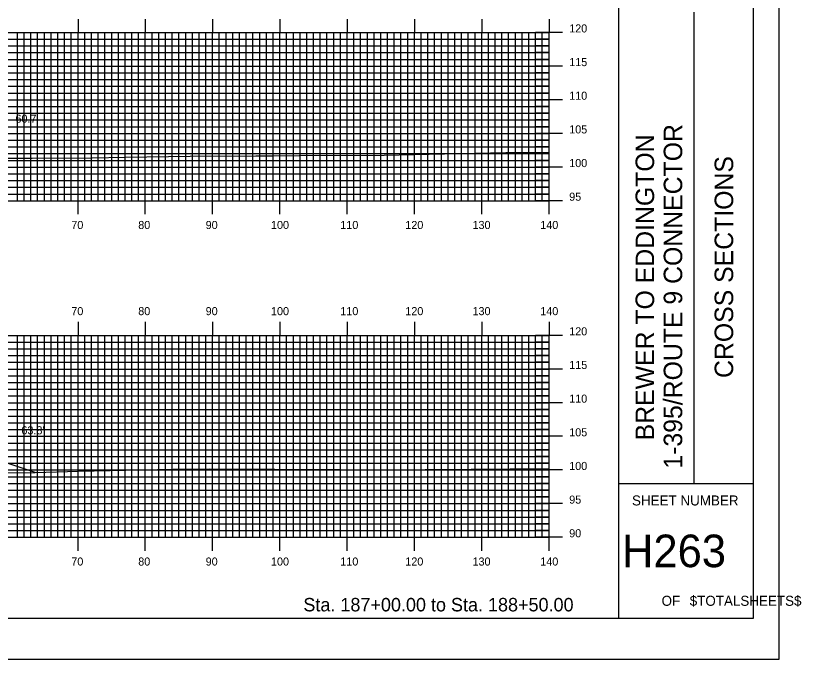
# Model space of a CAD drawing. Extents: x 1787763 to 1788106, y 442591 to 442811.
# Drawn here: x 1787989.4 to 1788106.1, y 442590.5 to 442686.2 of the extents above; entities that cross this region are included whole.
import ezdxf

# ---------------------------------------------------------------- set-up
doc = ezdxf.new("R2010")
doc.units = 0
for name, color, linetype in [('BORDER', 7, 'Continuous'), ('D_Roadway_Centerline', 7, 'Continuous'), ('D_Roadway_SlopeLines', 7, 'Continuous'), ('D_Text_Standard', 7, 'Continuous'), ('H_V ANNOTATION', 7, 'Continuous'), ('MAJOR', 7, 'Continuous'), ('MINOR', 7, 'Continuous'), ('PLOT BOUNDARY', 7, 'Continuous'), ('S_Roadway_Centerline', 7, 'Continuous')]:
    doc.layers.add(name, color=color, linetype=linetype)

msp = doc.modelspace()

# ---------------------------------------------------------------- linework, layer by layer
at = {"layer": 'BORDER'}
for p, q in [((1788079.02, 442596.67), (1788079.02, 442806.67)), ((1788090.2, 442616.67), (1788090.2, 442686.67)), ((1788079.02, 442616.67), (1788099.02, 442616.67))]:
    msp.add_line(p, q, dxfattribs=at)
msp.add_lwpolyline([(1787779.02, 442596.67), (1788099.02, 442596.67), (1788099.02, 442806.67), (1787779.02, 442806.67)], close=True, dxfattribs=at)
at = {"layer": 'D_Roadway_Centerline'}
msp.add_lwpolyline([(1787864.55, 442617.68), (1787896.62, 442628.37), (1787900.25, 442629.27), (1787908.62, 442631.37), (1787916.62, 442631.69), (1787928.62, 442631.95), (1787940.62, 442632.21), (1787948.62, 442631.89), (1787956.98, 442629.8), (1787960.62, 442628.89), (1787992.37, 442618.31)], dxfattribs=at)
at = {"layer": 'D_Roadway_SlopeLines'}
msp.add_lwpolyline([(1787948.62, 442631.89), (1787960.62, 442628.89), (1787992.37, 442618.31)], dxfattribs=at)
at = {"layer": 'MAJOR'}
for p, q in [((1787998.62, 442685.67), (1787998.62, 442683.67)), ((1788008.62, 442685.67), (1788008.62, 442683.67)), ((1788018.62, 442685.67), (1788018.62, 442683.67)), ((1788028.62, 442685.67), (1788028.62, 442683.67)), ((1788038.62, 442685.67), (1788038.62, 442683.67)), ((1788048.62, 442685.67), (1788048.62, 442683.67)), ((1788058.62, 442685.67), (1788058.62, 442683.67)), ((1788068.62, 442685.67), (1788068.62, 442683.67)), ((1787788.62, 442683.67), (1788068.62, 442683.67)), ((1787788.62, 442683.67), (1788068.62, 442683.67)), ((1787998.62, 442658.67), (1787998.62, 442683.67)), ((1788008.62, 442658.67), (1788008.62, 442683.67)), ((1788018.62, 442658.67), (1788018.62, 442683.67)), ((1788028.62, 442658.67), (1788028.62, 442683.67)), ((1788038.62, 442658.67), (1788038.62, 442683.67)), ((1788048.62, 442658.67), (1788048.62, 442683.67)), ((1788058.62, 442658.67), (1788058.62, 442683.67)), ((1788070.62, 442683.67), (1788066.61, 442683.67)), ((1788068.62, 442658.67), (1788068.62, 442683.67)), ((1788068.62, 442658.67), (1788068.62, 442683.67)), ((1787788.62, 442678.67), (1788068.62, 442678.67)), ((1788070.62, 442678.67), (1788066.61, 442678.67)), ((1787788.62, 442673.67), (1788068.62, 442673.67)), ((1788070.62, 442673.67), (1788066.61, 442673.67)), ((1787788.62, 442668.67), (1788068.62, 442668.67)), ((1788070.62, 442668.67), (1788066.61, 442668.67)), ((1787788.62, 442663.67), (1788068.62, 442663.67)), ((1788070.62, 442663.67), (1788066.61, 442663.67)), ((1787788.62, 442658.67), (1788068.62, 442658.67)), ((1787788.62, 442658.67), (1788068.62, 442658.67)), ((1787998.62, 442656.66), (1787998.62, 442658.67)), ((1788008.62, 442656.66), (1788008.62, 442658.67)), ((1788018.62, 442656.66), (1788018.62, 442658.67)), ((1788028.62, 442656.66), (1788028.62, 442658.67)), ((1788038.62, 442656.66), (1788038.62, 442658.67)), ((1788048.62, 442656.66), (1788048.62, 442658.67)), ((1788058.62, 442656.66), (1788058.62, 442658.67)), ((1788070.62, 442658.67), (1788066.61, 442658.67)), ((1788068.62, 442656.66), (1788068.62, 442658.67)), ((1787998.62, 442640.67), (1787998.62, 442638.67)), ((1788008.62, 442640.67), (1788008.62, 442638.67)), ((1788018.62, 442640.67), (1788018.62, 442638.67)), ((1788028.62, 442640.67), (1788028.62, 442638.67)), ((1788038.62, 442640.67), (1788038.62, 442638.67)), ((1788048.62, 442640.67), (1788048.62, 442638.67)), ((1788058.62, 442640.67), (1788058.62, 442638.67)), ((1788068.62, 442640.67), (1788068.62, 442638.67)), ((1787788.62, 442638.67), (1788068.62, 442638.67)), ((1787788.62, 442638.67), (1788068.62, 442638.67)), ((1787998.62, 442608.67), (1787998.62, 442638.67)), ((1788008.62, 442608.67), (1788008.62, 442638.67)), ((1788018.62, 442608.67), (1788018.62, 442638.67)), ((1788028.62, 442608.67), (1788028.62, 442638.67)), ((1788038.62, 442608.67), (1788038.62, 442638.67)), ((1788048.62, 442608.67), (1788048.62, 442638.67)), ((1788058.62, 442608.67), (1788058.62, 442638.67)), ((1788070.62, 442638.67), (1788066.61, 442638.67)), ((1788068.62, 442608.67), (1788068.62, 442638.67)), ((1788068.62, 442608.67), (1788068.62, 442638.67)), ((1787788.62, 442633.67), (1788068.62, 442633.67)), ((1788070.62, 442633.67), (1788066.61, 442633.67)), ((1787788.62, 442628.67), (1788068.62, 442628.67)), ((1788070.62, 442628.67), (1788066.61, 442628.67)), ((1787788.62, 442623.67), (1788068.62, 442623.67)), ((1788070.62, 442623.67), (1788066.61, 442623.67)), ((1787788.62, 442618.67), (1788068.62, 442618.67)), ((1788070.62, 442618.67), (1788066.61, 442618.67)), ((1787788.62, 442613.67), (1788068.62, 442613.67)), ((1788070.62, 442613.67), (1788066.61, 442613.67)), ((1787788.62, 442608.67), (1788068.62, 442608.67)), ((1787788.62, 442608.67), (1788068.62, 442608.67)), ((1787998.62, 442606.66), (1787998.62, 442608.67)), ((1788008.62, 442606.66), (1788008.62, 442608.67)), ((1788018.62, 442606.66), (1788018.62, 442608.67)), ((1788028.62, 442606.66), (1788028.62, 442608.67)), ((1788038.62, 442606.66), (1788038.62, 442608.67)), ((1788048.62, 442606.66), (1788048.62, 442608.67)), ((1788058.62, 442606.66), (1788058.62, 442608.67)), ((1788070.62, 442608.67), (1788066.61, 442608.67)), ((1788068.62, 442606.66), (1788068.62, 442608.67))]:
    msp.add_line(p, q, dxfattribs=at)
at = {"layer": 'MINOR'}
for p, q in [((1787788.62, 442682.67), (1788068.62, 442682.67)), ((1787989.62, 442658.67), (1787989.62, 442683.67)), ((1787990.62, 442658.67), (1787990.62, 442683.67)), ((1787991.62, 442658.67), (1787991.62, 442683.67)), ((1787992.62, 442658.67), (1787992.62, 442683.67)), ((1787993.62, 442658.67), (1787993.62, 442683.67)), ((1787994.62, 442658.67), (1787994.62, 442683.67)), ((1787995.62, 442658.67), (1787995.62, 442683.67)), ((1787996.62, 442658.67), (1787996.62, 442683.67)), ((1787997.62, 442658.67), (1787997.62, 442683.67)), ((1787999.62, 442658.67), (1787999.62, 442683.67)), ((1788000.62, 442658.67), (1788000.62, 442683.67)), ((1788001.62, 442658.67), (1788001.62, 442683.67)), ((1788002.62, 442658.67), (1788002.62, 442683.67)), ((1788003.62, 442658.67), (1788003.62, 442683.67)), ((1788004.62, 442658.67), (1788004.62, 442683.67)), ((1788005.62, 442658.67), (1788005.62, 442683.67)), ((1788006.62, 442658.67), (1788006.62, 442683.67)), ((1788007.62, 442658.67), (1788007.62, 442683.67)), ((1788009.62, 442658.67), (1788009.62, 442683.67)), ((1788010.62, 442658.67), (1788010.62, 442683.67)), ((1788011.62, 442658.67), (1788011.62, 442683.67)), ((1788012.62, 442658.67), (1788012.62, 442683.67)), ((1788013.62, 442658.67), (1788013.62, 442683.67)), ((1788014.62, 442658.67), (1788014.62, 442683.67)), ((1788015.62, 442658.67), (1788015.62, 442683.67)), ((1788016.62, 442658.67), (1788016.62, 442683.67)), ((1788017.62, 442658.67), (1788017.62, 442683.67)), ((1788019.62, 442658.67), (1788019.62, 442683.67)), ((1788020.62, 442658.67), (1788020.62, 442683.67)), ((1788021.62, 442658.67), (1788021.62, 442683.67)), ((1788022.62, 442658.67), (1788022.62, 442683.67)), ((1788023.62, 442658.67), (1788023.62, 442683.67)), ((1788024.62, 442658.67), (1788024.62, 442683.67)), ((1788025.62, 442658.67), (1788025.62, 442683.67)), ((1788026.62, 442658.67), (1788026.62, 442683.67)), ((1788027.62, 442658.67), (1788027.62, 442683.67)), ((1788029.62, 442658.67), (1788029.62, 442683.67)), ((1788030.62, 442658.67), (1788030.62, 442683.67)), ((1788031.62, 442658.67), (1788031.62, 442683.67)), ((1788032.62, 442658.67), (1788032.62, 442683.67)), ((1788033.62, 442658.67), (1788033.62, 442683.67)), ((1788034.62, 442658.67), (1788034.62, 442683.67)), ((1788035.62, 442658.67), (1788035.62, 442683.67)), ((1788036.62, 442658.67), (1788036.62, 442683.67)), ((1788037.62, 442658.67), (1788037.62, 442683.67)), ((1788039.62, 442658.67), (1788039.62, 442683.67)), ((1788040.62, 442658.67), (1788040.62, 442683.67)), ((1788041.62, 442658.67), (1788041.62, 442683.67)), ((1788042.62, 442658.67), (1788042.62, 442683.67)), ((1788043.62, 442658.67), (1788043.62, 442683.67)), ((1788044.62, 442658.67), (1788044.62, 442683.67)), ((1788045.62, 442658.67), (1788045.62, 442683.67)), ((1788046.62, 442658.67), (1788046.62, 442683.67)), ((1788047.62, 442658.67), (1788047.62, 442683.67)), ((1788049.62, 442658.67), (1788049.62, 442683.67)), ((1788050.62, 442658.67), (1788050.62, 442683.67)), ((1788051.62, 442658.67), (1788051.62, 442683.67)), ((1788052.62, 442658.67), (1788052.62, 442683.67)), ((1788053.62, 442658.67), (1788053.62, 442683.67)), ((1788054.62, 442658.67), (1788054.62, 442683.67)), ((1788055.62, 442658.67), (1788055.62, 442683.67)), ((1788056.62, 442658.67), (1788056.62, 442683.67)), ((1788057.62, 442658.67), (1788057.62, 442683.67)), ((1788059.62, 442658.67), (1788059.62, 442683.67)), ((1788060.62, 442658.67), (1788060.62, 442683.67)), ((1788061.62, 442658.67), (1788061.62, 442683.67)), ((1788062.62, 442658.67), (1788062.62, 442683.67)), ((1788063.62, 442658.67), (1788063.62, 442683.67)), ((1788064.62, 442658.67), (1788064.62, 442683.67)), ((1788065.62, 442658.67), (1788065.62, 442683.67)), ((1788068.62, 442682.67), (1788066.61, 442682.67)), ((1788066.62, 442658.67), (1788066.62, 442683.67)), ((1788067.62, 442658.67), (1788067.62, 442683.67)), ((1787788.62, 442681.67), (1788068.62, 442681.67)), ((1788068.62, 442681.67), (1788066.61, 442681.67)), ((1787788.62, 442680.67), (1788068.62, 442680.67)), ((1788068.62, 442680.67), (1788066.61, 442680.67)), ((1787788.62, 442679.67), (1788068.62, 442679.67)), ((1788068.62, 442679.67), (1788066.61, 442679.67)), ((1787788.62, 442677.67), (1788068.62, 442677.67)), ((1788068.62, 442677.67), (1788066.61, 442677.67)), ((1787788.62, 442676.67), (1788068.62, 442676.67)), ((1787788.62, 442675.67), (1788068.62, 442675.67)), ((1788068.62, 442676.67), (1788066.61, 442676.67)), ((1788068.62, 442675.67), (1788066.61, 442675.67)), ((1787788.62, 442674.67), (1788068.62, 442674.67)), ((1788068.62, 442674.67), (1788066.61, 442674.67)), ((1787788.62, 442672.67), (1788068.62, 442672.67)), ((1788068.62, 442672.67), (1788066.61, 442672.67)), ((1787788.62, 442671.67), (1788068.62, 442671.67)), ((1788068.62, 442671.67), (1788066.61, 442671.67)), ((1787788.62, 442670.67), (1788068.62, 442670.67)), ((1788068.62, 442670.67), (1788066.61, 442670.67)), ((1787788.62, 442669.67), (1788068.62, 442669.67)), ((1788068.62, 442669.67), (1788066.61, 442669.67)), ((1787788.62, 442667.67), (1788068.62, 442667.67)), ((1788068.62, 442667.67), (1788066.61, 442667.67)), ((1787788.62, 442666.67), (1788068.62, 442666.67)), ((1788068.62, 442666.67), (1788066.61, 442666.67)), ((1787788.62, 442665.67), (1788068.62, 442665.67)), ((1788068.62, 442665.67), (1788066.61, 442665.67)), ((1787788.62, 442664.67), (1788068.62, 442664.67)), ((1788068.62, 442664.67), (1788066.61, 442664.67)), ((1787788.62, 442662.67), (1788068.62, 442662.67)), ((1787788.62, 442661.67), (1788068.62, 442661.67)), ((1788068.62, 442662.67), (1788066.61, 442662.67)), ((1788068.62, 442661.67), (1788066.61, 442661.67)), ((1787788.62, 442660.67), (1788068.62, 442660.67)), ((1788068.62, 442660.67), (1788066.61, 442660.67)), ((1787788.62, 442659.67), (1788068.62, 442659.67)), ((1788068.62, 442659.67), (1788066.61, 442659.67)), ((1787989.62, 442608.67), (1787989.62, 442638.67)), ((1787990.62, 442608.67), (1787990.62, 442638.67)), ((1787991.62, 442608.67), (1787991.62, 442638.67)), ((1787992.62, 442608.67), (1787992.62, 442638.67)), ((1787993.62, 442608.67), (1787993.62, 442638.67)), ((1787994.62, 442608.67), (1787994.62, 442638.67)), ((1787995.62, 442608.67), (1787995.62, 442638.67)), ((1787996.62, 442608.67), (1787996.62, 442638.67)), ((1787997.62, 442608.67), (1787997.62, 442638.67)), ((1787999.62, 442608.67), (1787999.62, 442638.67)), ((1788000.62, 442608.67), (1788000.62, 442638.67)), ((1788001.62, 442608.67), (1788001.62, 442638.67)), ((1788002.62, 442608.67), (1788002.62, 442638.67)), ((1788003.62, 442608.67), (1788003.62, 442638.67)), ((1788004.62, 442608.67), (1788004.62, 442638.67)), ((1788005.62, 442608.67), (1788005.62, 442638.67)), ((1788006.62, 442608.67), (1788006.62, 442638.67)), ((1788007.62, 442608.67), (1788007.62, 442638.67)), ((1788009.62, 442608.67), (1788009.62, 442638.67)), ((1788010.62, 442608.67), (1788010.62, 442638.67)), ((1788011.62, 442608.67), (1788011.62, 442638.67)), ((1788012.62, 442608.67), (1788012.62, 442638.67)), ((1788013.62, 442608.67), (1788013.62, 442638.67)), ((1788014.62, 442608.67), (1788014.62, 442638.67)), ((1788015.62, 442608.67), (1788015.62, 442638.67)), ((1788016.62, 442608.67), (1788016.62, 442638.67)), ((1788017.62, 442608.67), (1788017.62, 442638.67)), ((1788019.62, 442608.67), (1788019.62, 442638.67)), ((1788020.62, 442608.67), (1788020.62, 442638.67)), ((1788021.62, 442608.67), (1788021.62, 442638.67)), ((1788022.62, 442608.67), (1788022.62, 442638.67)), ((1788023.62, 442608.67), (1788023.62, 442638.67)), ((1788024.62, 442608.67), (1788024.62, 442638.67)), ((1788025.62, 442608.67), (1788025.62, 442638.67)), ((1788026.62, 442608.67), (1788026.62, 442638.67)), ((1788027.62, 442608.67), (1788027.62, 442638.67)), ((1788029.62, 442608.67), (1788029.62, 442638.67)), ((1788030.62, 442608.67), (1788030.62, 442638.67)), ((1788031.62, 442608.67), (1788031.62, 442638.67)), ((1788032.62, 442608.67), (1788032.62, 442638.67)), ((1788033.62, 442608.67), (1788033.62, 442638.67)), ((1788034.62, 442608.67), (1788034.62, 442638.67)), ((1788035.62, 442608.67), (1788035.62, 442638.67)), ((1788036.62, 442608.67), (1788036.62, 442638.67)), ((1788037.62, 442608.67), (1788037.62, 442638.67)), ((1788039.62, 442608.67), (1788039.62, 442638.67)), ((1788040.62, 442608.67), (1788040.62, 442638.67)), ((1788041.62, 442608.67), (1788041.62, 442638.67)), ((1788042.62, 442608.67), (1788042.62, 442638.67)), ((1788043.62, 442608.67), (1788043.62, 442638.67)), ((1788044.62, 442608.67), (1788044.62, 442638.67)), ((1788045.62, 442608.67), (1788045.62, 442638.67)), ((1788046.62, 442608.67), (1788046.62, 442638.67)), ((1788047.62, 442608.67), (1788047.62, 442638.67)), ((1788049.62, 442608.67), (1788049.62, 442638.67)), ((1788050.62, 442608.67), (1788050.62, 442638.67)), ((1788051.62, 442608.67), (1788051.62, 442638.67)), ((1788052.62, 442608.67), (1788052.62, 442638.67)), ((1788053.62, 442608.67), (1788053.62, 442638.67)), ((1788054.62, 442608.67), (1788054.62, 442638.67)), ((1788055.62, 442608.67), (1788055.62, 442638.67)), ((1788056.62, 442608.67), (1788056.62, 442638.67)), ((1788057.62, 442608.67), (1788057.62, 442638.67)), ((1788059.62, 442608.67), (1788059.62, 442638.67)), ((1788060.62, 442608.67), (1788060.62, 442638.67)), ((1788061.62, 442608.67), (1788061.62, 442638.67)), ((1788062.62, 442608.67), (1788062.62, 442638.67)), ((1788063.62, 442608.67), (1788063.62, 442638.67)), ((1788064.62, 442608.67), (1788064.62, 442638.67)), ((1788065.62, 442608.67), (1788065.62, 442638.67)), ((1788066.62, 442608.67), (1788066.62, 442638.67)), ((1788067.62, 442608.67), (1788067.62, 442638.67)), ((1787788.62, 442637.67), (1788068.62, 442637.67)), ((1788068.62, 442637.67), (1788066.61, 442637.67)), ((1787788.62, 442636.67), (1788068.62, 442636.67)), ((1788068.62, 442636.67), (1788066.61, 442636.67)), ((1787788.62, 442635.67), (1788068.62, 442635.67)), ((1788068.62, 442635.67), (1788066.61, 442635.67)), ((1787788.62, 442634.67), (1788068.62, 442634.67)), ((1788068.62, 442634.67), (1788066.61, 442634.67)), ((1787788.62, 442632.67), (1788068.62, 442632.67)), ((1788068.62, 442632.67), (1788066.61, 442632.67)), ((1787788.62, 442631.67), (1788068.62, 442631.67)), ((1788068.62, 442631.67), (1788066.61, 442631.67)), ((1787788.62, 442630.67), (1788068.62, 442630.67)), ((1788068.62, 442630.67), (1788066.61, 442630.67)), ((1787788.62, 442629.67), (1788068.62, 442629.67)), ((1788068.62, 442629.67), (1788066.61, 442629.67)), ((1787788.62, 442627.67), (1788068.62, 442627.67)), ((1787788.62, 442626.67), (1788068.62, 442626.67)), ((1788068.62, 442627.67), (1788066.61, 442627.67)), ((1788068.62, 442626.67), (1788066.61, 442626.67)), ((1787788.62, 442625.67), (1788068.62, 442625.67)), ((1788068.62, 442625.67), (1788066.61, 442625.67)), ((1787788.62, 442624.67), (1788068.62, 442624.67)), ((1788068.62, 442624.67), (1788066.61, 442624.67)), ((1787788.62, 442622.67), (1788068.62, 442622.67)), ((1788068.62, 442622.67), (1788066.61, 442622.67)), ((1787788.62, 442621.67), (1788068.62, 442621.67)), ((1788068.62, 442621.67), (1788066.61, 442621.67)), ((1787788.62, 442620.67), (1788068.62, 442620.67)), ((1787788.62, 442619.67), (1788068.62, 442619.67)), ((1788068.62, 442620.67), (1788066.61, 442620.67)), ((1788068.62, 442619.67), (1788066.61, 442619.67)), ((1787788.62, 442617.67), (1788068.62, 442617.67)), ((1788068.62, 442617.67), (1788066.61, 442617.67)), ((1787788.62, 442616.67), (1788068.62, 442616.67)), ((1788068.62, 442616.67), (1788066.61, 442616.67)), ((1787788.62, 442615.67), (1788068.62, 442615.67)), ((1788068.62, 442615.67), (1788066.61, 442615.67)), ((1787788.62, 442614.67), (1788068.62, 442614.67)), ((1788068.62, 442614.67), (1788066.61, 442614.67)), ((1787788.62, 442612.67), (1788068.62, 442612.67)), ((1788068.62, 442612.67), (1788066.61, 442612.67)), ((1787788.62, 442611.67), (1788068.62, 442611.67)), ((1788068.62, 442611.67), (1788066.61, 442611.67)), ((1787788.62, 442610.67), (1788068.62, 442610.67)), ((1788068.62, 442610.67), (1788066.61, 442610.67)), ((1787788.62, 442609.67), (1788068.62, 442609.67)), ((1788068.62, 442609.67), (1788066.61, 442609.67))]:
    msp.add_line(p, q, dxfattribs=at)
at = {"layer": 'PLOT BOUNDARY'}
msp.add_lwpolyline([(1787762.83, 442590.55), (1788102.83, 442590.55), (1788102.83, 442810.55), (1787762.83, 442810.55)], close=True, dxfattribs=at)
at = {"layer": 'S_Roadway_Centerline'}
for points in [[(1787986.43, 442664.99), (1787991.8, 442665.02), (1788000.73, 442665.06), (1788005.62, 442665.12), (1788015.27, 442665.31), (1788025.03, 442665.36), (1788027.64, 442665.35), (1788031.48, 442665.41), (1788044.1, 442665.46), (1788050.82, 442665.58), (1788062.18, 442665.83), (1788063.97, 442665.85), (1788066.79, 442665.86), (1788068.62, 442665.87)], [(1787981.81, 442618.19), (1787992.2, 442618.3), (1787998.69, 442618.5), (1788012.75, 442618.8), (1788018.11, 442618.86), (1788027.86, 442618.79), (1788037.51, 442618.72), (1788043.31, 442618.71), (1788057.05, 442618.8), (1788068.62, 442618.91)]]:
    msp.add_lwpolyline(points, dxfattribs=at)

# ---------------------------------------------------------------- texts
at = {"layer": 'BORDER'}
for s, p in [('1-395/ROUTE 9 CONNECTOR', (1788088.42, 442618.87)), ('BREWER TO EDDINGTON', (1788084.24, 442623.07)), ('CROSS SECTIONS', (1788095.99, 442632.34))]:
    msp.add_text(s, height=2.7557, rotation=90, dxfattribs=at).set_placement(p)
for s, height, p in [('SHEET NUMBER', 1.4905, (1788080.95, 442613.4)), ('H263', 4.839, (1788079.46, 442604.23)), ('OF', 1.491, (1788085.35, 442598.49)), ('$TOTALSHEETS$', 1.4905, (1788089.53, 442598.49))]:
    msp.add_text(s, height=height, dxfattribs=at).set_placement(p)
at = {"layer": 'D_Text_Standard'}
for s, p in [("60.7'", (1787989.32, 442670.26)), ("63.8'", (1787990.2, 442623.97))]:
    msp.add_text(s, height=1.2, dxfattribs=at).set_placement(p)
at = {"layer": 'H_V ANNOTATION'}
for s, height, p in [('120', 1.2, (1788071.62, 442683.67)), ('115', 1.2, (1788071.62, 442678.67)), ('110', 1.2, (1788071.62, 442673.67)), ('105', 1.2, (1788071.62, 442668.67)), ('100', 1.2, (1788071.62, 442663.67)), ('95', 1.2, (1788071.62, 442658.67)), ('70', 1.2, (1787997.62, 442654.47)), ('80', 1.2, (1788007.57, 442654.47)), ('90', 1.2, (1788017.59, 442654.47)), ('100', 1.2, (1788027.3, 442654.47)), ('110', 1.2, (1788037.6, 442654.47)), ('120', 1.2, (1788047.26, 442654.47)), ('130', 1.2, (1788057.25, 442654.47)), ('140', 1.2, (1788067.32, 442654.47)), ('70', 1.2, (1787997.62, 442641.67)), ('80', 1.2, (1788007.57, 442641.67)), ('90', 1.2, (1788017.59, 442641.67)), ('100', 1.2, (1788027.3, 442641.67)), ('110', 1.2, (1788037.6, 442641.67)), ('120', 1.2, (1788047.26, 442641.67)), ('130', 1.2, (1788057.25, 442641.67)), ('140', 1.2, (1788067.32, 442641.67)), ('120', 1.2, (1788071.62, 442638.67)), ('115', 1.2, (1788071.62, 442633.67)), ('110', 1.2, (1788071.62, 442628.67)), ('105', 1.2, (1788071.62, 442623.67)), ('100', 1.2, (1788071.62, 442618.67)), ('95', 1.2, (1788071.62, 442613.67)), ('90', 1.2, (1788071.62, 442608.67)), ('70', 1.2, (1787997.62, 442604.47)), ('80', 1.2, (1788007.57, 442604.47)), ('90', 1.2, (1788017.59, 442604.47)), ('100', 1.2, (1788027.3, 442604.47)), ('110', 1.2, (1788037.6, 442604.47)), ('120', 1.2, (1788047.26, 442604.47)), ('130', 1.2, (1788057.25, 442604.47)), ('140', 1.2, (1788067.32, 442604.47)), ('Sta. 187+00.00 to Sta. 188+50.00', 2.0004, (1788032.11, 442597.66))]:
    msp.add_text(s, height=height, dxfattribs=at).set_placement(p)

doc.saveas('drawing.dxf')
